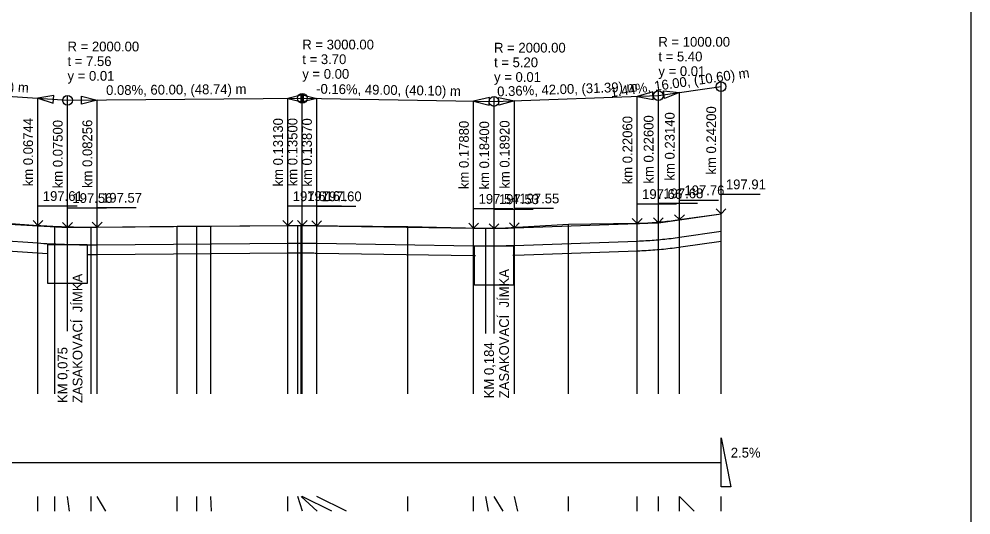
# Model space of a CAD drawing. Extents: x -24.9 to 20.5, y -71.8 to 17.3.
# Drawn here: x -3.79 to 20.54, y -58.57 to -45.89 of the extents above; entities that cross this region are included whole.
import ezdxf

# ---------------------------------------------------------------- set-up
doc = ezdxf.new("R2010")
doc.units = 0
for name, color, linetype in [('Implicitní', 7, 'Continuous'), ('KONSTRUKCE_L', 7, 'Continuous'), ('KOTY_L', 7, 'Continuous'), ('Nová vrstva (0)', 7, 'Continuous'), ('PR_SKLON_L', 7, 'Continuous'), ('PR_SKLON_T', 7, 'Continuous'), ('SKLON_POMERY', 7, 'Continuous'), ('TEREN_L', 7, 'Continuous'), ('V_POLYGON', 7, 'Continuous'), ('V_POLYGON_ZO', 7, 'Continuous')]:
    doc.layers.add(name, color=color, linetype=linetype)

msp = doc.modelspace()

# ---------------------------------------------------------------- linework, layer by layer
at = {"layer": 'Implicitní'}
msp.add_lwpolyline([(-24.886, -42.093), (20.536, -42.093), (20.536, -71.793), (-24.886, -71.793)], close=True, dxfattribs=at)
at = {"layer": 'KONSTRUKCE_L'}
for p, q in [((13.088, -51.47), (14.148, -51.318)), ((-6.85, -51.378), (-3.309, -51.617)), ((8.868, -51.679), (12.007, -51.567)), ((12.007, -51.567), (12.061, -51.565)), ((12.061, -51.565), (12.115, -51.562)), ((12.115, -51.562), (12.169, -51.56)), ((12.169, -51.56), (12.223, -51.557)), ((12.223, -51.557), (12.277, -51.553)), ((12.277, -51.553), (12.331, -51.55)), ((12.331, -51.55), (12.385, -51.546)), ((12.385, -51.546), (12.439, -51.542)), ((12.439, -51.542), (12.494, -51.538)), ((12.494, -51.538), (12.548, -51.533)), ((12.548, -51.533), (12.602, -51.528)), ((12.602, -51.528), (12.656, -51.523)), ((12.656, -51.523), (12.71, -51.517)), ((12.71, -51.517), (12.764, -51.511)), ((12.764, -51.511), (12.818, -51.505)), ((12.818, -51.505), (12.872, -51.499)), ((12.872, -51.499), (12.926, -51.492)), ((12.926, -51.492), (12.98, -51.485)), ((12.98, -51.485), (13.034, -51.477)), ((13.034, -51.477), (13.088, -51.47)), ((-3.309, -51.617), (-3.233, -51.622)), ((-3.233, -51.622), (-3.158, -51.626)), ((-3.158, -51.626), (-3.082, -51.631)), ((-3.082, -51.631), (-3.006, -51.635)), ((-3.006, -51.635), (-2.931, -51.638)), ((-2.931, -51.638), (-2.855, -51.642)), ((-2.855, -51.642), (-2.779, -51.645)), ((-2.779, -51.645), (-2.704, -51.648)), ((-2.704, -51.648), (-2.628, -51.651)), ((-2.628, -51.651), (-2.552, -51.653)), ((-2.552, -51.653), (-2.477, -51.655)), ((-2.477, -51.655), (-2.401, -51.657)), ((-2.401, -51.657), (-2.326, -51.659)), ((-2.326, -51.659), (-2.25, -51.66)), ((-2.25, -51.66), (-2.174, -51.661)), ((-2.174, -51.661), (-2.099, -51.661)), ((-2.099, -51.661), (-2.023, -51.662)), ((-2.023, -51.662), (-1.947, -51.662)), ((-1.947, -51.662), (-1.872, -51.662)), ((-1.872, -51.662), (-1.796, -51.661)), ((-1.796, -51.661), (3.078, -51.621)), ((3.078, -51.621), (3.115, -51.62)), ((3.115, -51.62), (3.152, -51.62)), ((3.152, -51.62), (3.189, -51.62)), ((3.189, -51.62), (3.226, -51.62)), ((3.226, -51.62), (3.263, -51.62)), ((3.263, -51.62), (3.3, -51.62)), ((3.3, -51.62), (3.337, -51.62)), ((3.337, -51.62), (3.374, -51.62)), ((3.374, -51.62), (3.411, -51.62)), ((3.411, -51.62), (3.448, -51.62)), ((3.448, -51.62), (3.485, -51.62)), ((3.485, -51.62), (3.522, -51.62)), ((3.522, -51.62), (3.559, -51.62)), ((3.559, -51.62), (3.595, -51.621)), ((3.595, -51.621), (3.632, -51.621)), ((3.632, -51.621), (3.669, -51.621)), ((3.669, -51.621), (3.706, -51.622)), ((3.706, -51.622), (3.743, -51.622)), ((3.743, -51.622), (3.78, -51.623)), ((3.78, -51.623), (3.817, -51.624)), ((3.817, -51.624), (7.827, -51.689)), ((7.827, -51.689), (7.879, -51.69)), ((7.879, -51.69), (7.931, -51.69)), ((7.931, -51.69), (7.983, -51.691)), ((7.983, -51.691), (8.035, -51.691)), ((8.035, -51.691), (8.087, -51.692)), ((8.087, -51.692), (8.139, -51.692)), ((8.139, -51.692), (8.191, -51.692)), ((8.191, -51.692), (8.243, -51.691)), ((8.243, -51.691), (8.295, -51.691)), ((8.295, -51.691), (8.348, -51.691)), ((8.348, -51.691), (8.4, -51.69)), ((8.4, -51.69), (8.452, -51.689)), ((8.452, -51.689), (8.504, -51.689)), ((8.504, -51.689), (8.556, -51.688)), ((8.556, -51.688), (8.608, -51.687)), ((8.608, -51.687), (8.66, -51.685)), ((8.66, -51.685), (8.712, -51.684)), ((8.712, -51.684), (8.764, -51.682)), ((8.764, -51.682), (8.816, -51.681)), ((8.816, -51.681), (8.868, -51.679))]:
    msp.add_line(p, q, dxfattribs=at)
at = {"layer": 'KOTY_L'}
for p, q in [((13.088, -55.478), (13.088, -51.02)), ((13.088, -55.478), (13.088, -51.02)), ((14.148, -55.478), (14.148, -50.868)), ((-3.309, -55.478), (-3.309, -51.174)), ((-2.873, -55.478), (-2.873, -51.199)), ((-2.552, -53.874), (-2.552, -51.218)), ((-1.947, -55.478), (-1.947, -51.211)), ((-1.796, -55.478), (-1.796, -51.209)), ((0.248, -55.478), (0.248, -51.188)), ((0.755, -55.478), (0.755, -51.184)), ((1.108, -55.478), (1.108, -51.182)), ((3.078, -55.478), (3.078, -51.17)), ((3.337, -55.478), (3.337, -51.168)), ((3.417, -55.478), (3.417, -51.168)), ((3.448, -55.478), (3.448, -51.168)), ((3.817, -55.478), (3.817, -51.172)), ((6.148, -55.478), (6.148, -51.198)), ((7.827, -55.478), (7.827, -51.236)), ((8.139, -53.932), (8.139, -51.243)), ((8.348, -53.932), (8.348, -51.248)), ((8.868, -55.478), (8.868, -51.217)), ((10.248, -55.478), (10.248, -51.138)), ((12.007, -55.478), (12.007, -51.107)), ((12.548, -55.478), (12.548, -51.098)), ((-3.309, -58.478), (-3.309, -58.103)), ((-2.873, -58.478), (-2.873, -58.103)), ((-2.498, -58.478), (-2.552, -58.103)), ((-1.947, -58.478), (-1.947, -58.103)), ((-1.572, -58.478), (-1.796, -58.103)), ((0.248, -58.478), (0.248, -58.103)), ((0.755, -58.478), (0.755, -58.103)), ((1.13, -58.478), (1.108, -58.103)), ((3.078, -58.478), (3.078, -58.103)), ((3.453, -58.478), (3.337, -58.103)), ((3.828, -58.478), (3.417, -58.103)), ((4.203, -58.478), (3.448, -58.103)), ((4.578, -58.478), (3.817, -58.103)), ((6.148, -58.478), (6.148, -58.103)), ((7.827, -58.478), (7.827, -58.103)), ((8.202, -58.478), (8.139, -58.103)), ((8.577, -58.478), (8.348, -58.103)), ((8.952, -58.478), (8.868, -58.103)), ((10.248, -58.478), (10.248, -58.103)), ((12.007, -58.478), (12.007, -58.103)), ((12.548, -58.478), (12.548, -58.103)), ((13.088, -58.478), (13.088, -58.103)), ((13.463, -58.478), (13.088, -58.103)), ((14.148, -58.478), (14.148, -58.103))]:
    msp.add_line(p, q, dxfattribs=at)
at = {"layer": 'Nová vrstva (0)'}
for p, q in [((13.123, -51.717), (14.148, -51.57)), ((-6.867, -51.628), (-3.06, -51.884)), ((8.877, -51.929), (12.016, -51.817)), ((12.017, -51.817), (12.071, -51.815)), ((12.072, -51.814), (12.126, -51.812)), ((12.128, -51.812), (12.182, -51.809)), ((12.183, -51.809), (12.237, -51.806)), ((12.238, -51.806), (12.292, -51.803)), ((12.294, -51.803), (12.348, -51.799)), ((12.349, -51.799), (12.403, -51.796)), ((12.404, -51.795), (12.458, -51.791)), ((12.46, -51.791), (12.514, -51.787)), ((12.515, -51.787), (12.569, -51.782)), ((12.571, -51.782), (12.625, -51.777)), ((12.626, -51.777), (12.68, -51.771)), ((12.681, -51.771), (12.735, -51.766)), ((12.737, -51.766), (12.791, -51.76)), ((12.792, -51.76), (12.846, -51.753)), ((12.847, -51.753), (12.901, -51.747)), ((12.903, -51.747), (12.957, -51.74)), ((12.958, -51.74), (13.012, -51.733)), ((13.013, -51.733), (13.067, -51.725)), ((13.069, -51.725), (13.123, -51.717)), ((-2.051, -51.912), (-2.024, -51.912)), ((-2.023, -51.912), (-1.948, -51.912)), ((-1.947, -51.912), (-1.871, -51.912)), ((-1.87, -51.912), (-1.794, -51.911)), ((-1.794, -51.911), (3.08, -51.871)), ((3.08, -51.871), (3.117, -51.87)), ((3.116, -51.87), (3.153, -51.87)), ((3.153, -51.87), (3.19, -51.87)), ((3.19, -51.87), (3.227, -51.87)), ((3.226, -51.87), (3.263, -51.87)), ((3.263, -51.87), (3.3, -51.87)), ((3.3, -51.87), (3.337, -51.87)), ((3.336, -51.87), (3.373, -51.87)), ((3.373, -51.87), (3.41, -51.87)), ((3.41, -51.87), (3.447, -51.87)), ((3.446, -51.87), (3.483, -51.87)), ((3.483, -51.87), (3.52, -51.87)), ((3.52, -51.87), (3.557, -51.87)), ((3.556, -51.87), (3.593, -51.871)), ((3.593, -51.871), (3.63, -51.871)), ((3.63, -51.871), (3.667, -51.871)), ((3.666, -51.871), (3.703, -51.872)), ((3.703, -51.872), (3.74, -51.872)), ((3.74, -51.872), (3.777, -51.873)), ((3.777, -51.873), (3.814, -51.874)), ((3.813, -51.874), (7.823, -51.939)), ((7.823, -51.939), (7.875, -51.94)), ((8.825, -51.931), (8.877, -51.929))]:
    msp.add_line(p, q, dxfattribs=at)
for points in [[(-3.052, -51.653), (-2.052, -51.653), (-2.052, -52.653), (-3.052, -52.653)], [(7.848, -51.691), (8.848, -51.691), (8.848, -52.691), (7.848, -52.691)]]:
    msp.add_lwpolyline(points, close=True, dxfattribs=at)
at = {"layer": 'PR_SKLON_L'}
msp.add_line((-10.052, -57.228), (14.148, -57.228), dxfattribs=at)
msp.add_lwpolyline([(14.148, -57.228), (14.148, -56.603), (14.398, -57.853), (14.148, -57.853)], close=True, dxfattribs=at)
at = {"layer": 'SKLON_POMERY'}
for p, q in [((-7.752, -47.618), (-2.552, -47.968)), ((12.548, -47.848), (14.148, -47.618)), ((14.148, -47.618), (14.148, -47.493)), ((14.148, -50.868), (14.148, -47.618)), ((-3.309, -51.167), (-3.309, -47.917)), ((-2.552, -47.968), (-2.552, -47.843)), ((-2.552, -47.968), (3.448, -47.918)), ((3.078, -51.171), (3.078, -47.921)), ((3.448, -47.918), (3.448, -47.793)), ((3.448, -51.168), (3.448, -47.918)), ((3.448, -47.918), (8.348, -47.998)), ((3.817, -51.174), (3.817, -47.924)), ((8.348, -47.998), (12.548, -47.848)), ((8.348, -47.998), (8.348, -47.873)), ((12.007, -51.117), (12.007, -47.867)), ((12.548, -47.848), (12.548, -47.723)), ((12.548, -51.098), (12.548, -47.848)), ((13.088, -51.02), (13.088, -47.77)), ((-2.552, -51.218), (-2.552, -47.968)), ((-1.796, -51.211), (-1.796, -47.961)), ((7.827, -51.239), (7.827, -47.989)), ((8.348, -51.248), (8.348, -47.998)), ((8.868, -51.229), (8.868, -47.979))]:
    msp.add_line(p, q, dxfattribs=at)
for points in [[(-3.309, -47.917), (-2.916, -48.043), (-2.903, -47.844), (-3.309, -47.917)], [(-1.796, -47.961), (-2.195, -48.065), (-2.197, -47.865), (-1.796, -47.961)], [(3.078, -47.921), (3.478, -48.017), (3.477, -47.817), (3.078, -47.921)], [(3.817, -47.924), (3.416, -48.017), (3.419, -47.817), (3.817, -47.924)], [(7.827, -47.989), (8.225, -48.096), (8.229, -47.896), (7.827, -47.989)], [(8.868, -47.979), (8.472, -48.093), (8.465, -47.893), (8.868, -47.979)], [(12.007, -47.867), (12.411, -47.952), (12.404, -47.753), (12.007, -47.867)], [(13.088, -47.77), (12.706, -47.926), (12.678, -47.728), (13.088, -47.77)]]:
    msp.add_lwpolyline(points, close=True, dxfattribs=at)
for points in [[(12.423, -50.973), (12.548, -51.098), (12.673, -50.973), (12.548, -51.098), (12.548, -50.598), (13.548, -50.598)], [(12.963, -50.895), (13.088, -51.02), (13.213, -50.895), (13.088, -51.02), (13.088, -50.52), (14.088, -50.52)], [(14.023, -50.743), (14.148, -50.868), (14.273, -50.743), (14.148, -50.868), (14.148, -50.368), (15.148, -50.368)], [(-3.434, -51.042), (-3.309, -51.167), (-3.184, -51.042), (-3.309, -51.167), (-3.309, -50.667), (-2.309, -50.667)], [(-2.677, -51.093), (-2.552, -51.218), (-2.427, -51.093), (-2.552, -51.218), (-2.552, -50.718), (-1.552, -50.718)], [(-1.921, -51.086), (-1.796, -51.211), (-1.671, -51.086), (-1.796, -51.211), (-1.796, -50.711), (-0.796, -50.711)], [(2.953, -51.046), (3.078, -51.171), (3.203, -51.046), (3.078, -51.171), (3.078, -50.671), (4.078, -50.671)], [(3.323, -51.043), (3.448, -51.168), (3.573, -51.043), (3.448, -51.168), (3.448, -50.668), (4.448, -50.668)], [(3.692, -51.049), (3.817, -51.174), (3.942, -51.049), (3.817, -51.174), (3.817, -50.674), (4.817, -50.674)], [(7.702, -51.114), (7.827, -51.239), (7.952, -51.114), (7.827, -51.239), (7.827, -50.739), (8.827, -50.739)], [(8.223, -51.123), (8.348, -51.248), (8.473, -51.123), (8.348, -51.248), (8.348, -50.748), (9.348, -50.748)], [(8.743, -51.104), (8.868, -51.229), (8.993, -51.104), (8.868, -51.229), (8.868, -50.729), (9.868, -50.729)], [(11.882, -50.992), (12.007, -51.117), (12.132, -50.992), (12.007, -51.117), (12.007, -50.617), (13.007, -50.617)]]:
    msp.add_lwpolyline(points, dxfattribs=at)
for centre in [(14.148, -47.618), (-2.552, -47.968), (3.448, -47.918), (8.348, -47.998), (12.548, -47.848)]:
    msp.add_circle(centre, 0.125, dxfattribs=at)
at = {"layer": 'TEREN_L'}
for p, q in [((-5.152, -51.068), (-2.552, -51.218)), ((12.548, -51.098), (14.148, -50.868)), ((-2.552, -51.218), (0.248, -51.188)), ((0.248, -51.188), (3.448, -51.168)), ((3.448, -51.168), (6.148, -51.198)), ((6.148, -51.198), (8.348, -51.248)), ((8.348, -51.248), (10.248, -51.138)), ((10.248, -51.138), (12.548, -51.098))]:
    msp.add_line(p, q, dxfattribs=at)
at = {"layer": 'V_POLYGON'}
for p, q in [((-6.85, -50.928), (-3.309, -51.167)), ((13.088, -51.02), (14.148, -50.868)), ((-1.796, -51.211), (3.078, -51.171)), ((3.817, -51.174), (7.827, -51.239)), ((8.868, -51.229), (12.007, -51.117))]:
    msp.add_line(p, q, dxfattribs=at)
for points in [[(12.007, -51.117), (12.061, -51.115), (12.115, -51.112), (12.169, -51.11), (12.223, -51.107), (12.277, -51.103), (12.331, -51.1), (12.385, -51.096), (12.439, -51.092), (12.494, -51.088), (12.548, -51.083), (12.602, -51.078), (12.656, -51.073), (12.71, -51.067), (12.764, -51.061), (12.818, -51.055), (12.872, -51.049), (12.926, -51.042), (12.98, -51.035), (13.034, -51.027), (13.088, -51.02)], [(-3.309, -51.167), (-3.233, -51.172), (-3.158, -51.176), (-3.082, -51.181), (-3.006, -51.185), (-2.931, -51.188), (-2.855, -51.192), (-2.779, -51.195), (-2.704, -51.198), (-2.628, -51.201), (-2.552, -51.203), (-2.477, -51.205), (-2.401, -51.207), (-2.326, -51.209), (-2.25, -51.21), (-2.174, -51.211), (-2.099, -51.211), (-2.023, -51.212), (-1.947, -51.212), (-1.872, -51.212), (-1.796, -51.211)], [(3.078, -51.171), (3.115, -51.17), (3.152, -51.17), (3.189, -51.17), (3.226, -51.17), (3.263, -51.17), (3.3, -51.17), (3.337, -51.17), (3.374, -51.17), (3.411, -51.17), (3.448, -51.17), (3.485, -51.17), (3.522, -51.17), (3.559, -51.17), (3.595, -51.171), (3.632, -51.171), (3.669, -51.171), (3.706, -51.172), (3.743, -51.172), (3.78, -51.173), (3.817, -51.174)], [(7.827, -51.239), (7.879, -51.24), (7.931, -51.24), (7.983, -51.241), (8.035, -51.241), (8.087, -51.242), (8.139, -51.242), (8.191, -51.242), (8.243, -51.241), (8.295, -51.241), (8.348, -51.241), (8.4, -51.24), (8.452, -51.239), (8.504, -51.239), (8.556, -51.238), (8.608, -51.237), (8.66, -51.235), (8.712, -51.234), (8.764, -51.232), (8.816, -51.231), (8.868, -51.229)]]:
    msp.add_lwpolyline(points, dxfattribs=at)
at = {"layer": 'V_POLYGON_ZO'}
for p, q in [((12.548, -51.098), (13.088, -51.02)), ((-3.309, -51.167), (-2.552, -51.218)), ((-2.552, -51.218), (-1.796, -51.211)), ((3.078, -51.171), (3.448, -51.168)), ((3.448, -51.168), (3.817, -51.174)), ((7.827, -51.239), (8.348, -51.248)), ((8.348, -51.248), (8.868, -51.229)), ((12.007, -51.117), (12.548, -51.098))]:
    msp.add_line(p, q, dxfattribs=at)

# ---------------------------------------------------------------- texts
at = {"layer": 'Nová vrstva (0)'}
for s, p in [('ZASAKOVACÍ  JÍMKA', (8.729, -55.588)), ('ZASAKOVACÍ  JÍMKA', (-2.171, -55.709)), ('KM 0,184', (8.345, -55.588)), ('KM 0,075', (-2.555, -55.709))]:
    msp.add_text(s, height=0.25, rotation=90, dxfattribs=at).set_placement(p)
at = {"layer": 'PR_SKLON_T'}
msp.add_text('2.5%', height=0.25, dxfattribs=at).set_placement((14.398, -57.103))
at = {"layer": 'SKLON_POMERY'}
for s, p in [('R = 2000.00', (-2.552, -46.718)), ('R = 3000.00', (3.448, -46.668)), ('R = 1000.00', (12.548, -46.598)), ('R = 2000.00', (8.348, -46.748)), ('t = 7.56', (-2.552, -47.093)), ('t = 3.70', (3.448, -47.043)), ('t = 5.20', (8.348, -47.123)), ('t = 5.40', (12.548, -46.973)), ('y = 0.00', (3.448, -47.418)), ('y = 0.01', (12.548, -47.348)), ('y = 0.01', (-2.552, -47.468)), ('y = 0.01', (8.348, -47.498)), ('197.91', (14.273, -50.243)), ('197.61', (-3.184, -50.542)), ('197.56', (-2.427, -50.593)), ('197.57', (-1.671, -50.586)), ('197.61', (3.203, -50.546)), ('197.61', (3.573, -50.543)), ('197.60', (3.942, -50.549)), ('197.55', (8.993, -50.604)), ('197.66', (12.132, -50.492)), ('197.68', (12.673, -50.473)), ('197.76', (13.213, -50.395)), ('197.54', (7.952, -50.614)), ('197.53', (8.473, -50.623))]:
    msp.add_text(s, height=0.25, dxfattribs=at).set_placement(p)
for s, rotation, p in [('1.44%, 16.00, (10.60) m', 8.1802, (11.338, -47.893)), ('-0.67%, 52.00, (35.41) m', 356.1494, (-7.239, -47.526)), ('0.08%, 60.00, (48.74) m', 0.4774, (-1.566, -47.834)), ('-0.16%, 49.00, (40.10) m', 359.0646, (3.8, -47.798)), ('0.36%, 42.00, (31.39) m', 2.0454, (8.432, -47.869)), ('km 0.24200', 90, (14.023, -49.868)), ('km 0.22060', 90, (11.882, -50.117)), ('km 0.22600', 90, (12.423, -50.098)), ('km 0.23140', 90, (12.963, -50.02)), ('km 0.06744', 90, (-3.434, -50.167)), ('km 0.07500', 90, (-2.677, -50.218)), ('km 0.08256', 90, (-1.921, -50.211)), ('km 0.13130', 90, (2.953, -50.171)), ('km 0.13500', 90, (3.323, -50.168)), ('km 0.13870', 90, (3.692, -50.174)), ('km 0.17880', 90, (7.702, -50.239)), ('km 0.18400', 90, (8.223, -50.248)), ('km 0.18920', 90, (8.743, -50.229))]:
    msp.add_text(s, height=0.25, rotation=rotation, dxfattribs=at).set_placement(p)

doc.saveas('drawing.dxf')
